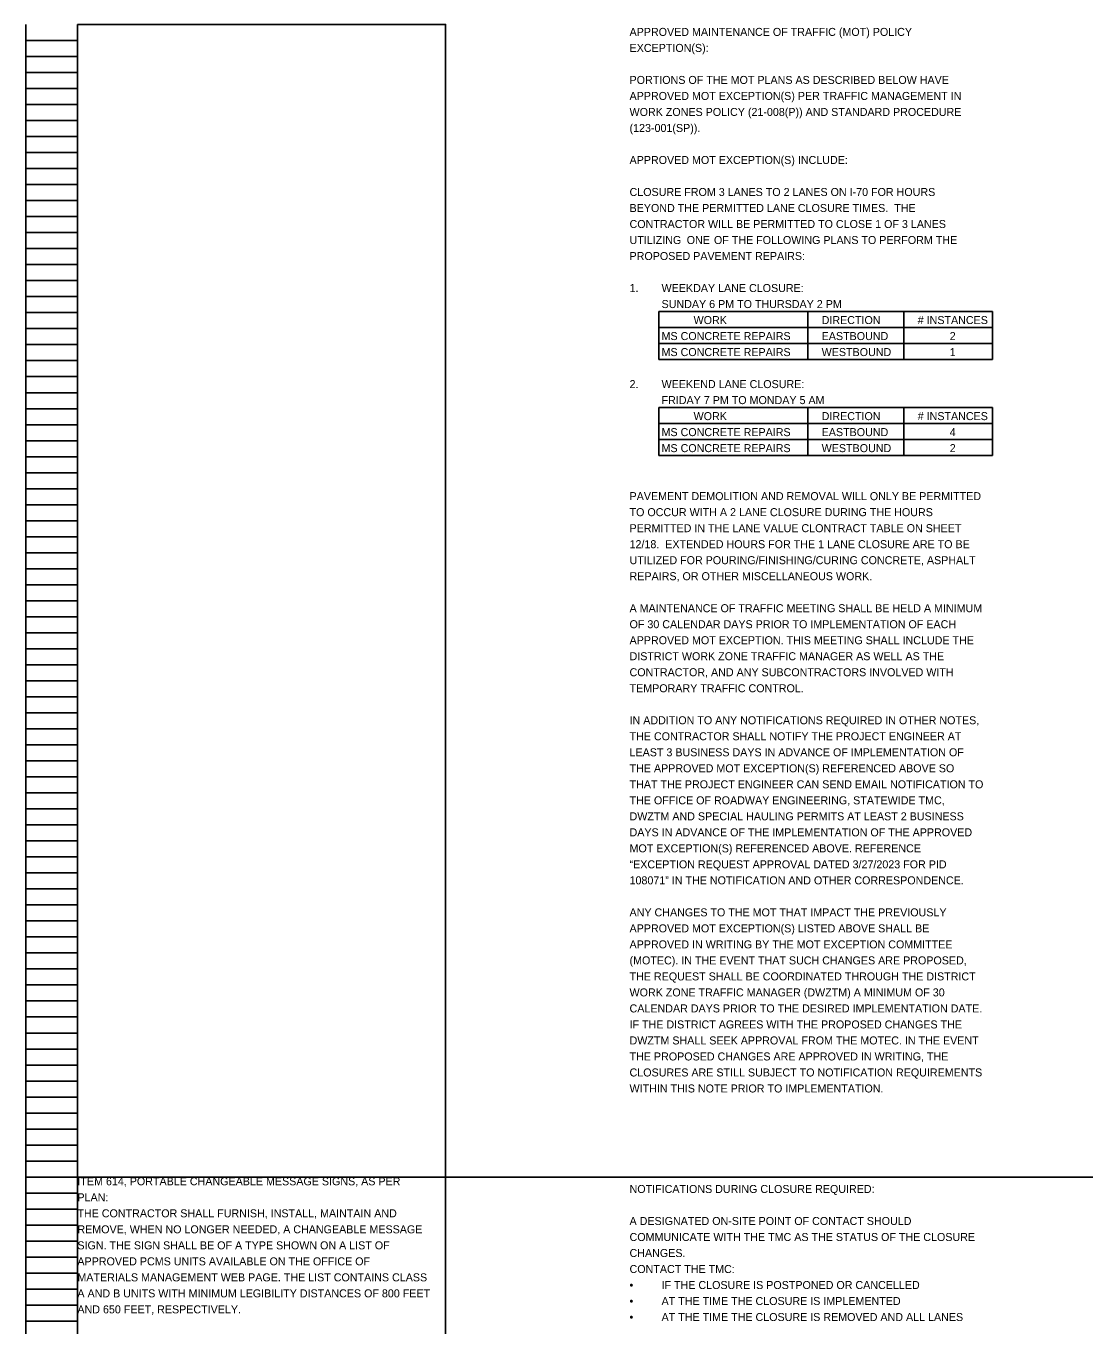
# Model space of a CAD drawing. Extents: x 16463 to 16500, y 5400 to 5823.
# Drawn here: x 16463.05 to 16481.55, y 5740.24 to 5762.97 of the extents above; entities that cross this region are included whole.
import ezdxf

# ---------------------------------------------------------------- set-up
doc = ezdxf.new("R2010")
doc.units = 0
for name, color, linetype in [('Default', 7, 'Continuous'), ('SC_Scratch1', 7, 'Continuous'), ('SH_Data', 7, 'Continuous')]:
    doc.layers.add(name, color=color, linetype=linetype)

msp = doc.modelspace()

# ---------------------------------------------------------------- linework, layer by layer
at = {"layer": 'Default'}
for p, q in [((16474.116, 5757.972), (16479.952, 5757.972)), ((16474.116, 5757.972), (16474.116, 5757.132)), ((16476.725, 5757.972), (16476.725, 5757.132)), ((16478.406, 5757.972), (16478.406, 5757.132)), ((16479.952, 5757.972), (16479.952, 5757.132)), ((16474.116, 5757.692), (16479.952, 5757.692)), ((16474.116, 5757.412), (16479.952, 5757.412)), ((16474.116, 5757.132), (16479.952, 5757.132)), ((16474.116, 5756.292), (16479.952, 5756.292)), ((16474.116, 5756.292), (16474.116, 5755.452)), ((16476.725, 5756.292), (16476.725, 5755.452)), ((16478.406, 5756.292), (16478.406, 5755.452)), ((16479.952, 5756.292), (16479.952, 5755.452)), ((16474.116, 5756.012), (16479.952, 5756.012)), ((16474.116, 5755.732), (16479.952, 5755.732)), ((16474.116, 5755.452), (16479.952, 5755.452))]:
    msp.add_line(p, q, dxfattribs=at)
at = {"layer": 'SC_Scratch1'}
msp.add_line((16470.389, 5742.832), (16500.06, 5742.832), dxfattribs=at)
for points in [[(16463.949, 5762.992), (16470.389, 5762.992), (16470.389, 5742.832), (16463.949, 5742.832)], [(16463.949, 5742.832), (16470.389, 5742.832), (16470.389, 5722.672), (16463.949, 5722.672)]]:
    msp.add_lwpolyline(points, close=True, dxfattribs=at)
at = {"layer": 'SH_Data'}
for p, q in [((16463.049, 5742.832), (16463.049, 5762.992)), ((16463.949, 5742.832), (16463.949, 5762.992)), ((16463.049, 5762.712), (16463.949, 5762.712)), ((16463.049, 5762.432), (16463.949, 5762.432)), ((16463.049, 5762.152), (16463.949, 5762.152)), ((16463.049, 5761.872), (16463.949, 5761.872)), ((16463.049, 5761.592), (16463.949, 5761.592)), ((16463.049, 5761.312), (16463.949, 5761.312)), ((16463.049, 5761.032), (16463.949, 5761.032)), ((16463.049, 5760.752), (16463.949, 5760.752)), ((16463.049, 5760.472), (16463.949, 5760.472)), ((16463.049, 5760.192), (16463.949, 5760.192)), ((16463.049, 5759.912), (16463.949, 5759.912)), ((16463.049, 5759.632), (16463.949, 5759.632)), ((16463.049, 5759.352), (16463.949, 5759.352)), ((16463.049, 5759.072), (16463.949, 5759.072)), ((16463.049, 5758.792), (16463.949, 5758.792)), ((16463.049, 5758.512), (16463.949, 5758.512)), ((16463.049, 5758.232), (16463.949, 5758.232)), ((16463.049, 5757.952), (16463.949, 5757.952)), ((16463.049, 5757.672), (16463.949, 5757.672)), ((16463.049, 5757.392), (16463.949, 5757.392)), ((16463.049, 5757.112), (16463.949, 5757.112)), ((16463.049, 5756.832), (16463.949, 5756.832)), ((16463.049, 5756.552), (16463.949, 5756.552)), ((16463.049, 5756.272), (16463.949, 5756.272)), ((16463.049, 5755.992), (16463.949, 5755.992)), ((16463.049, 5755.712), (16463.949, 5755.712)), ((16463.049, 5755.432), (16463.949, 5755.432)), ((16463.049, 5755.152), (16463.949, 5755.152)), ((16463.049, 5754.872), (16463.949, 5754.872)), ((16463.049, 5754.592), (16463.949, 5754.592)), ((16463.049, 5754.312), (16463.949, 5754.312)), ((16463.049, 5754.032), (16463.949, 5754.032)), ((16463.049, 5753.752), (16463.949, 5753.752)), ((16463.049, 5753.472), (16463.949, 5753.472)), ((16463.049, 5753.192), (16463.949, 5753.192)), ((16463.049, 5752.912), (16463.949, 5752.912)), ((16463.049, 5752.632), (16463.949, 5752.632)), ((16463.049, 5752.352), (16463.949, 5752.352)), ((16463.049, 5752.072), (16463.949, 5752.072)), ((16463.049, 5751.792), (16463.949, 5751.792)), ((16463.049, 5751.512), (16463.949, 5751.512)), ((16463.049, 5751.232), (16463.949, 5751.232)), ((16463.049, 5750.952), (16463.949, 5750.952)), ((16463.049, 5750.672), (16463.949, 5750.672)), ((16463.049, 5750.392), (16463.949, 5750.392)), ((16463.049, 5750.112), (16463.949, 5750.112)), ((16463.049, 5749.832), (16463.949, 5749.832)), ((16463.049, 5749.552), (16463.949, 5749.552)), ((16463.049, 5749.272), (16463.949, 5749.272)), ((16463.049, 5748.992), (16463.949, 5748.992)), ((16463.049, 5748.712), (16463.949, 5748.712)), ((16463.049, 5748.432), (16463.949, 5748.432)), ((16463.049, 5748.152), (16463.949, 5748.152)), ((16463.049, 5747.872), (16463.949, 5747.872)), ((16463.049, 5747.592), (16463.949, 5747.592)), ((16463.049, 5747.312), (16463.949, 5747.312)), ((16463.049, 5747.032), (16463.949, 5747.032)), ((16463.049, 5746.752), (16463.949, 5746.752)), ((16463.049, 5746.472), (16463.949, 5746.472)), ((16463.049, 5746.192), (16463.949, 5746.192)), ((16463.049, 5745.912), (16463.949, 5745.912)), ((16463.049, 5745.632), (16463.949, 5745.632)), ((16463.049, 5745.352), (16463.949, 5745.352)), ((16463.049, 5745.072), (16463.949, 5745.072)), ((16463.049, 5744.792), (16463.949, 5744.792)), ((16463.049, 5744.512), (16463.949, 5744.512)), ((16463.049, 5744.232), (16463.949, 5744.232)), ((16463.049, 5743.952), (16463.949, 5743.952)), ((16463.049, 5743.672), (16463.949, 5743.672)), ((16463.049, 5743.392), (16463.949, 5743.392)), ((16463.049, 5743.112), (16463.949, 5743.112)), ((16463.049, 5722.672), (16463.049, 5742.832)), ((16463.049, 5742.832), (16463.949, 5742.832)), ((16463.049, 5742.832), (16463.949, 5742.832)), ((16463.949, 5722.672), (16463.949, 5742.832)), ((16463.049, 5742.552), (16463.949, 5742.552)), ((16463.049, 5742.272), (16463.949, 5742.272)), ((16463.049, 5741.992), (16463.949, 5741.992)), ((16463.049, 5741.712), (16463.949, 5741.712)), ((16463.049, 5741.432), (16463.949, 5741.432)), ((16463.049, 5741.152), (16463.949, 5741.152)), ((16463.049, 5740.872), (16463.949, 5740.872)), ((16463.049, 5740.592), (16463.949, 5740.592)), ((16463.049, 5740.312), (16463.949, 5740.312))]:
    msp.add_line(p, q, dxfattribs=at)

# ---------------------------------------------------------------- texts
at = {"layer": 'Default'}
for s, p in [('APPROVED MAINTENANCE OF TRAFFIC (MOT) POLICY ', (16473.606, 5762.792)), ('EXCEPTION(S):', (16473.606, 5762.512)), ('PORTIONS OF THE MOT PLANS AS DESCRIBED BELOW HAVE ', (16473.606, 5761.952)), ('APPROVED MOT EXCEPTION(S) PER TRAFFIC MANAGEMENT IN ', (16473.606, 5761.672)), ('WORK ZONES POLICY (21-008(P)) AND STANDARD PROCEDURE ', (16473.606, 5761.392)), ('(123-001(SP)). ', (16473.606, 5761.112)), ('APPROVED MOT EXCEPTION(S) INCLUDE: ', (16473.606, 5760.552)), ('CLOSURE FROM 3 LANES TO 2 LANES ON I-70 FOR HOURS ', (16473.606, 5759.992)), ('BEYOND THE PERMITTED LANE CLOSURE TIMES.  THE ', (16473.606, 5759.712)), ('CONTRACTOR WILL BE PERMITTED TO CLOSE 1 OF 3 LANES ', (16473.606, 5759.432)), ('UTILIZING ', (16473.606, 5759.152)), ('ONE', (16474.606, 5759.152)), (' OF THE FOLLOWING PLANS TO PERFORM THE ', (16475.03, 5759.152)), ('PROPOSED PAVEMENT REPAIRS:', (16473.606, 5758.872)), ('1.', (16473.606, 5758.312)), ('WEEKDAY LANE CLOSURE:', (16474.166, 5758.312)), ('SUNDAY 6 PM TO THURSDAY 2 PM', (16474.166, 5758.032)), ('WORK', (16474.726, 5757.752)), ('DIRECTION', (16476.966, 5757.752)), ('# INSTANCES', (16478.646, 5757.752)), ('MS CONCRETE REPAIRS', (16474.166, 5757.472)), ('EASTBOUND', (16476.966, 5757.472)), ('2', (16479.206, 5757.472)), ('MS CONCRETE REPAIRS', (16474.166, 5757.192)), ('WESTBOUND', (16476.966, 5757.192)), ('1', (16479.206, 5757.192)), ('2.', (16473.606, 5756.632)), ('WEEKEND LANE CLOSURE:', (16474.166, 5756.632)), ('FRIDAY 7 PM TO MONDAY 5 AM', (16474.166, 5756.352)), ('WORK', (16474.726, 5756.072)), ('DIRECTION', (16476.966, 5756.072)), ('# INSTANCES', (16478.646, 5756.072)), ('MS CONCRETE REPAIRS', (16474.166, 5755.792)), ('EASTBOUND', (16476.966, 5755.792)), ('4', (16479.206, 5755.792)), ('MS CONCRETE REPAIRS', (16474.166, 5755.512)), ('WESTBOUND', (16476.966, 5755.512)), ('2', (16479.206, 5755.512)), ('PAVEMENT DEMOLITION AND REMOVAL WILL ONLY BE PERMITTED ', (16473.606, 5754.672)), ('TO OCCUR WITH A 2 LANE CLOSURE DURING THE HOURS ', (16473.606, 5754.392)), ('PERMITTED IN THE LANE VALUE CLONTRACT TABLE ON SHEET ', (16473.606, 5754.112)), ('12/18.  EXTENDED HOURS FOR THE 1 LANE CLOSURE ARE TO BE ', (16473.606, 5753.832)), ('UTILIZED FOR POURING/FINISHING/CURING CONCRETE, ASPHALT ', (16473.606, 5753.552)), ('REPAIRS, OR OTHER MISCELLANEOUS WORK.', (16473.606, 5753.272)), ('A MAINTENANCE OF TRAFFIC MEETING SHALL BE HELD A MINIMUM ', (16473.606, 5752.712)), ('OF 30 CALENDAR DAYS PRIOR TO IMPLEMENTATION OF EACH ', (16473.606, 5752.432)), ('APPROVED MOT EXCEPTION. THIS MEETING SHALL INCLUDE THE ', (16473.606, 5752.152)), ('DISTRICT WORK ZONE TRAFFIC MANAGER AS WELL AS THE ', (16473.606, 5751.872)), ('CONTRACTOR, AND ANY SUBCONTRACTORS INVOLVED WITH ', (16473.606, 5751.592)), ('TEMPORARY TRAFFIC CONTROL. ', (16473.606, 5751.312)), ('IN ADDITION TO ANY NOTIFICATIONS REQUIRED IN OTHER NOTES, ', (16473.606, 5750.752)), ('THE CONTRACTOR SHALL NOTIFY THE PROJECT ENGINEER AT ', (16473.606, 5750.472)), ('LEAST 3 BUSINESS DAYS IN ADVANCE OF IMPLEMENTATION OF ', (16473.606, 5750.192)), ('THE APPROVED MOT EXCEPTION(S) REFERENCED ABOVE SO ', (16473.606, 5749.912)), ('THAT THE PROJECT ENGINEER CAN SEND EMAIL NOTIFICATION TO ', (16473.606, 5749.632)), ('THE OFFICE OF ROADWAY ENGINEERING, STATEWIDE TMC, ', (16473.606, 5749.352)), ('DWZTM AND SPECIAL HAULING PERMITS AT LEAST 2 BUSINESS ', (16473.606, 5749.072)), ('DAYS IN ADVANCE OF THE IMPLEMENTATION OF THE APPROVED ', (16473.606, 5748.792)), ('MOT EXCEPTION(S) REFERENCED ABOVE. REFERENCE ', (16473.606, 5748.512)), ('“EXCEPTION REQUEST APPROVAL DATED 3/27/2023 FOR PID ', (16473.606, 5748.232)), ('108071” IN THE NOTIFICATION AND OTHER CORRESPONDENCE. ', (16473.606, 5747.952)), ('ANY CHANGES TO THE MOT THAT IMPACT THE PREVIOUSLY ', (16473.606, 5747.392)), ('APPROVED MOT EXCEPTION(S) LISTED ABOVE SHALL BE ', (16473.606, 5747.112)), ('APPROVED IN WRITING BY THE MOT EXCEPTION COMMITTEE ', (16473.606, 5746.832)), ('(MOTEC). IN THE EVENT THAT SUCH CHANGES ARE PROPOSED, ', (16473.606, 5746.552)), ('THE REQUEST SHALL BE COORDINATED THROUGH THE DISTRICT ', (16473.606, 5746.272)), ('WORK ZONE TRAFFIC MANAGER (DWZTM) A MINIMUM OF 30 ', (16473.606, 5745.992)), ('CALENDAR DAYS PRIOR TO THE DESIRED IMPLEMENTATION DATE. ', (16473.606, 5745.712)), ('IF THE DISTRICT AGREES WITH THE PROPOSED CHANGES THE ', (16473.606, 5745.432)), ('DWZTM SHALL SEEK APPROVAL FROM THE MOTEC. IN THE EVENT ', (16473.606, 5745.152)), ('THE PROPOSED CHANGES ARE APPROVED IN WRITING, THE ', (16473.606, 5744.872)), ('CLOSURES ARE STILL SUBJECT TO NOTIFICATION REQUIREMENTS ', (16473.606, 5744.592)), ('WITHIN THIS NOTE PRIOR TO IMPLEMENTATION. ', (16473.606, 5744.312)), ('ITEM 614, PORTABLE CHANGEABLE MESSAGE SIGNS, AS PER ', (16463.949, 5742.688)), ('NOTIFICATIONS DURING CLOSURE REQUIRED:', (16473.606, 5742.554)), ('PLAN:', (16463.949, 5742.408)), ('THE CONTRACTOR SHALL FURNISH, INSTALL, MAINTAIN AND ', (16463.949, 5742.128)), ('REMOVE, WHEN NO LONGER NEEDED, A CHANGEABLE MESSAGE ', (16463.949, 5741.848)), ('A DESIGNATED ON-SITE POINT OF CONTACT SHOULD ', (16473.606, 5741.994)), ('SIGN. THE SIGN SHALL BE OF A TYPE SHOWN ON A LIST OF ', (16463.949, 5741.568)), ('COMMUNICATE WITH THE TMC AS THE STATUS OF THE CLOSURE ', (16473.606, 5741.714)), ('CHANGES.  ', (16473.606, 5741.434)), ('APPROVED PCMS UNITS AVAILABLE ON THE OFFICE OF ', (16463.949, 5741.288)), ('CONTACT THE TMC: ', (16473.606, 5741.154)), ('MATERIALS MANAGEMENT WEB PAGE. THE LIST CONTAINS CLASS ', (16463.949, 5741.008)), ('A AND B UNITS WITH MINIMUM LEGIBILITY DISTANCES OF 800 FEET ', (16463.949, 5740.728)), ('•', (16473.606, 5740.874)), ('IF THE CLOSURE IS POSTPONED OR CANCELLED', (16474.166, 5740.874)), ('AND 650 FEET, RESPECTIVELY. ', (16463.949, 5740.448)), ('•', (16473.606, 5740.594)), ('AT THE TIME THE CLOSURE IS IMPLEMENTED ', (16474.166, 5740.594)), ('•', (16473.606, 5740.314)), ('AT THE TIME THE CLOSURE IS REMOVED AND ALL LANES ', (16474.166, 5740.314))]:
    msp.add_text(s, height=0.14, dxfattribs=at).set_placement(p)

doc.saveas('drawing.dxf')
